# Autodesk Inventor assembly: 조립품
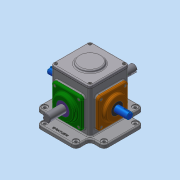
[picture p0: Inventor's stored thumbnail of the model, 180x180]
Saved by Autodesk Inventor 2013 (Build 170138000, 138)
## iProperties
Created: 2019-12
Part Number: 조립품
Document SubType Name: Assembly
Designer: dgall
Mass: 3662.21 g
Surface Area: 3562.97 cm^2
Volume: 1128.24 cm^3
Density: 3.24594 g/cm^3
Author: dgall
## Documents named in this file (16)
- C:\Users\dgall\Desktop\391204V1045\조립품.iam
- C:\Users\dgall\Desktop\391204V1045\개스킷.ipt
- C:\Users\dgall\Desktop\391204V1045\메인베벨기어.ipt
- C:\Users\dgall\Desktop\391204V1045\메인축.ipt
- C:\Users\dgall\Desktop\391204V1045\메인커버.ipt
- C:\Users\dgall\Desktop\391204V1045\베어링 6203.ipt
- C:\Users\dgall\Desktop\391204V1045\베어링 6204.ipt
- C:\Users\dgall\Desktop\391204V1045\본체.ipt
- C:\Users\dgall\Desktop\391204V1045\볼트 M4.ipt
- C:\Users\dgall\Desktop\391204V1045\상부커버.ipt
- C:\Users\dgall\Desktop\391204V1045\서브베벨기어.ipt
- C:\Users\dgall\Desktop\391204V1045\서브축.ipt
- C:\Users\dgall\Desktop\391204V1045\서브커버.ipt
- C:\Users\dgall\Desktop\391204V1045\오일 실 17 32 8.ipt
- C:\Users\dgall\Desktop\391204V1045\오일 실 20 35 8.ipt
- C:\Users\dgall\Desktop\391204V1045\키 4x4.ipt
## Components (1 placed, 1 different names)
1. 개스킷:1
